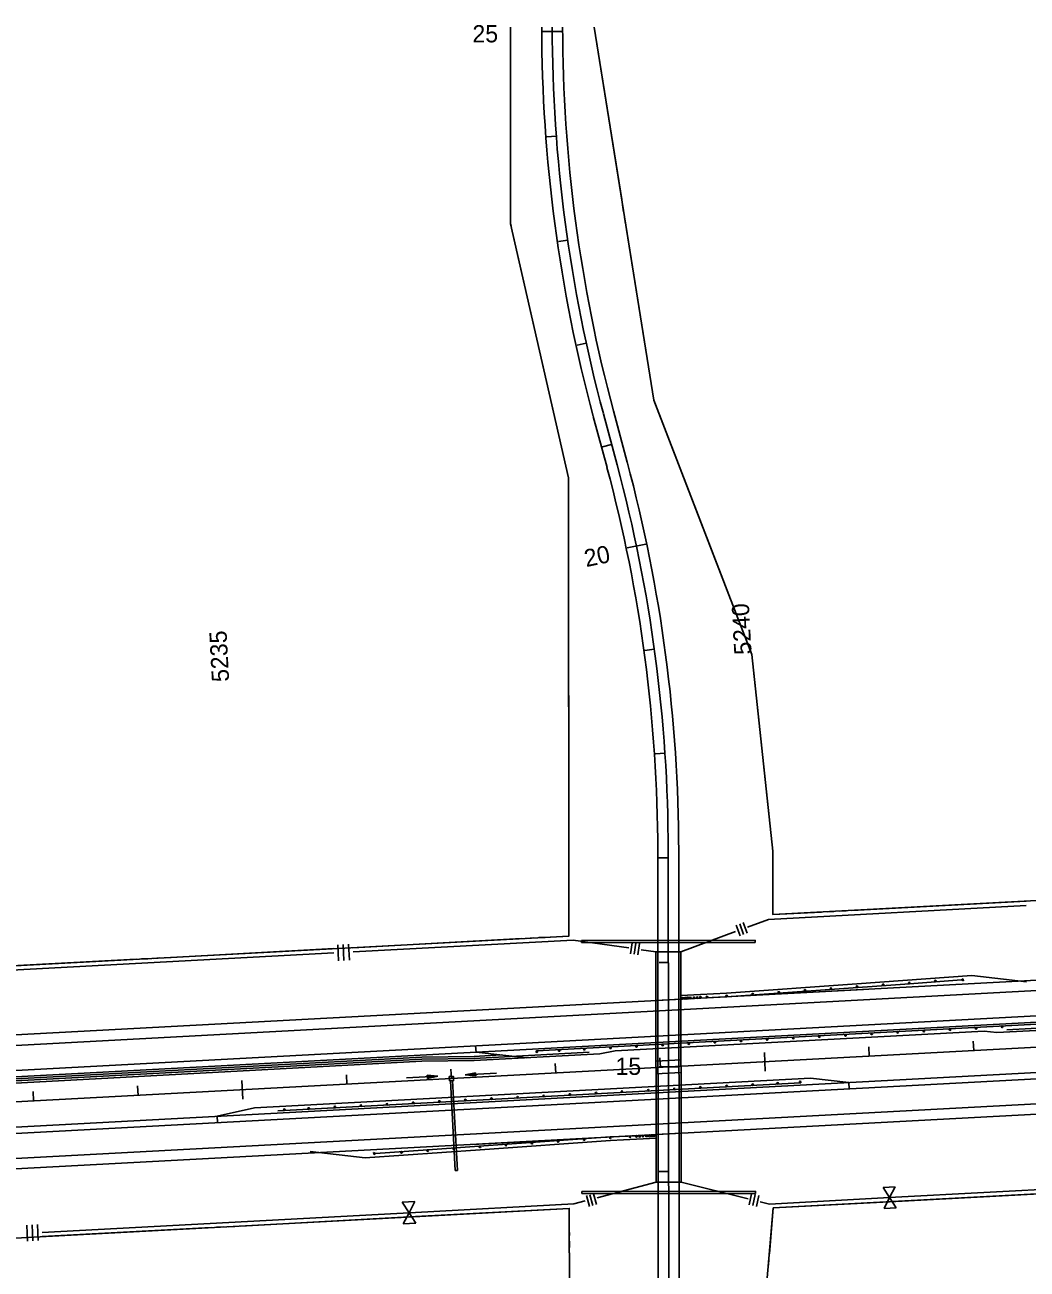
# Model space of a CAD drawing. Extents: x 192699 to 285914, y 194342 to 233219.
# Drawn here: x 267912 to 268870, y 225541 to 226731 of the extents above; entities that cross this region are included whole.
import ezdxf

# ---------------------------------------------------------------- set-up
doc = ezdxf.new("R2010")
doc.units = 0
for name, color, linetype in [('CENT LINE', 7, 'Continuous'), ('CONCRETE', 7, 'Continuous'), ('DRAINAGE', 7, 'Continuous'), ('DRAINAGE ARROWS', 7, 'Continuous'), ('GUARD RAILS', 7, 'Continuous'), ('GUARDRAIL', 7, 'Continuous'), ('R-W - CofA', 7, 'Continuous'), ('R_Draft', 7, 'Continuous'), ('R_Water Annot', 7, 'Continuous'), ('ROAD', 7, 'Continuous'), ('SHOULDER', 7, 'Continuous'), ('STATIONING1', 7, 'Continuous'), ('STATIONING2', 7, 'Continuous'), ('WRSF', 7, 'Continuous')]:
    doc.layers.add(name, color=color, linetype=linetype)

msp = doc.modelspace()

# ---------------------------------------------------------------- linework, layer by layer
at = {"layer": 'CENT LINE'}
for p, q in [((268415.7, 226728.5), (268415.7, 226728.5)), ((268477.7, 226310.2), (268464.6, 226359)), ((268527.8, 224960.5), (268526.6, 225940.8)), ((253740.3, 224942.3), (269263.7, 225774))]:
    msp.add_line(p, q, dxfattribs=at)
for centre, start, end in [((269848.1, 226730.2), 180.0667, 195.0168), ((267094.2, 225939.1), 0.0667, 15.0168)]:
    msp.add_arc(centre, 1432.4, start, end, dxfattribs=at)
at = {"layer": 'CONCRETE'}
for p, q in [((268960.4, 225773.8), (268840.6, 225767.3)), ((268828.5, 225768.7), (268476, 225749.8)), ((268828.5, 225768.7), (268840.6, 225767.3)), ((268367, 225746), (268341.1, 225744.6)), ((268461.1, 225747), (268341.2, 225740.6)), ((268342.9, 225748.7), (268342.5, 225754.7)), ((268342.9, 225748.7), (268391.2, 225743.3)), ((268461.1, 225747), (268476, 225749.8)), ((267077.8, 225678.9), (268291.1, 225743.9)), ((267078, 225674.9), (268291.2, 225739.9)), ((268341.1, 225744.6), (268291.1, 225743.9)), ((268341.2, 225740.6), (268291.2, 225739.9)), ((268131, 225695.3), (268662.7, 225723.8)), ((268699.2, 225719.7), (268662.7, 225723.8)), ((268699.2, 225719.7), (268699.7, 225713.7)), ((268095.4, 225687.4), (268131, 225695.3)), ((268095.4, 225687.4), (268095.7, 225681.4))]:
    msp.add_line(p, q, dxfattribs=at)
at = {"layer": 'DRAINAGE'}
for p, q in [((268443.7, 225855.4), (268609.7, 225855.6)), ((268443.7, 225853.4), (268609.7, 225853.6)), ((268318.5, 225721.3), (268323.1, 225635.5)), ((268320.5, 225721.4), (268325.1, 225635.6)), ((268444, 225615.4), (268610, 225615.6)), ((268444, 225613.4), (268610, 225613.6))]:
    msp.add_line(p, q, dxfattribs=at)
for points in [[(268443.7, 225853.4), (268443.7, 225855.4)], [(268609.7, 225853.6), (268609.7, 225855.6)], [(268323.1, 225635.5), (268325.1, 225635.6)], [(268444, 225613.4), (268444, 225615.4)], [(268610, 225613.6), (268610, 225615.6)]]:
    msp.add_lwpolyline(points, dxfattribs=at)
msp.add_lwpolyline([(268317.5, 225721.3), (268321.5, 225721.5), (268321.3, 225725.5), (268317.3, 225725.3)], close=True, dxfattribs=at)
at = {"layer": 'DRAINAGE ARROWS'}
for p, q in [((268296.2, 225726.5), (268306.3, 225725.6)), ((268296.4, 225723.5), (268296.2, 225726.5)), ((268296.2, 225726.3), (268304.6, 225725.5)), ((268296.3, 225726), (268302.9, 225725.4)), ((268296.3, 225725.8), (268301.3, 225725.3)), ((268296.3, 225725.5), (268299.6, 225725.2)), ((268296.3, 225725.3), (268297.9, 225725.1)), ((268296.3, 225724.6), (268299.6, 225725.2)), ((268296.3, 225724.8), (268297.9, 225725.1)), ((268296.4, 225723.5), (268306.3, 225725.6)), ((268296.4, 225723.8), (268304.6, 225725.5)), ((268296.4, 225724), (268302.9, 225725.4)), ((268296.4, 225724.3), (268301.3, 225725.3)), ((268342.5, 225729), (268332.6, 225727)), ((268342.6, 225726), (268332.6, 225727)), ((268342.5, 225728.8), (268334.2, 225727.1)), ((268342.6, 225726.3), (268334.2, 225727.1)), ((268342.5, 225728.5), (268336, 225727.2)), ((268342.6, 225726.5), (268336, 225727.2)), ((268342.5, 225728.3), (268337.6, 225727.3)), ((268342.6, 225726.8), (268337.6, 225727.3)), ((268342.5, 225728), (268339.3, 225727.4)), ((268342.6, 225727.1), (268339.3, 225727.4)), ((268342.6, 225727.8), (268341, 225727.4)), ((268342.6, 225727.3), (268341, 225727.4)), ((268342.6, 225726), (268342.5, 225729))]:
    msp.add_line(p, q, dxfattribs=at)
at = {"layer": 'GUARD RAILS'}
for p, q in [((268900.2, 225776.6), (268400.9, 225749.8)), ((268153.6, 225692.5), (268652.9, 225719.2))]:
    msp.add_line(p, q, dxfattribs=at)
for centre in [(268770.9, 225768.9), (268795.9, 225770.2), (268820.9, 225771.5), (268845.8, 225772.9), (268546.3, 225756.8), (268571.2, 225758.2), (268596.2, 225759.5), (268621.2, 225760.8), (268646.1, 225762.2), (268671.1, 225763.5), (268696.1, 225764.8), (268721, 225766.2), (268746, 225767.5), (268401, 225749.1), (268422.4, 225750.2), (268446.4, 225751.5), (268471.4, 225752.8), (268496.3, 225754.1), (268521.3, 225755.5), (268457.5, 225709.5), (268482.5, 225710.9), (268507.5, 225712.2), (268532.4, 225713.5), (268557.4, 225714.9), (268582.4, 225716.2), (268607.3, 225717.5), (268631.3, 225718.8), (268652.7, 225720), (268232.9, 225697.5), (268257.8, 225698.8), (268282.8, 225700.2), (268307.8, 225701.5), (268332.7, 225702.8), (268357.7, 225704.2), (268382.7, 225705.5), (268407.6, 225706.8), (268432.6, 225708.2), (268159.7, 225693.6), (268182.9, 225694.8), (268207.9, 225696.1)]:
    msp.add_circle(centre, 0.75, dxfattribs=at)
at = {"layer": 'GUARDRAIL'}
for p, q in [((268562.6, 225800.5), (268713.4, 225808.6)), ((268514.8, 225798), (268538.8, 225799.2)), ((268514.9, 225739.9), (268538.9, 225741.2)), ((268514.9, 225727.9), (268538.9, 225729.1)), ((268491.2, 225668.5), (268339.7, 225660.4)), ((268514.9, 225669.8), (268538.9, 225671.1))]:
    msp.add_line(p, q, dxfattribs=at)
at = {"layer": 'R-W - CofA'}
for p, q in [((268375.9, 226540.5), (268375.7, 226728.5)), ((268431.2, 226297.8), (268375.9, 226540.5)), ((268431.7, 225859.6), (268431.2, 226297.8)), ((268626.7, 225880.1), (269256.3, 225913.8)), ((268591.7, 225870), (268595.4, 225859.9)), ((268595, 225871.2), (268598.7, 225861.2)), ((268598.3, 225872.5), (268602.1, 225862.4)), ((268492, 225853.3), (268490.6, 225842.7)), ((268495.6, 225852.8), (268494.1, 225842.2)), ((268210.8, 225851.3), (268211.6, 225836)), ((268215.9, 225851.6), (268216.7, 225836.3)), ((268221, 225851.9), (268221.8, 225836.6)), ((268499.1, 225852.4), (268497.6, 225841.7)), ((268627, 225599.7), (269271.2, 225634.2)), ((268731.9, 225619.3), (268743.5, 225619.9)), ((268738.2, 225609.6), (268731.9, 225619.3)), ((268743.5, 225619.9), (268738.2, 225609.6)), ((268272.3, 225605.2), (268284.3, 225605.9)), ((268278.9, 225595.1), (268272.3, 225605.2)), ((268284.3, 225605.9), (268278.9, 225595.1)), ((268448.4, 225611.5), (268451.2, 225601.1)), ((268451.8, 225612.4), (268454.6, 225602.1)), ((268455.3, 225613.3), (268458.1, 225603)), ((268606.2, 225613.2), (268603.9, 225602.7)), ((268609.7, 225612.5), (268607.4, 225602)), ((268613.2, 225611.7), (268610.9, 225601.2)), ((268733, 225599.2), (268738.2, 225609.6)), ((268738.2, 225609.6), (268744.6, 225599.9)), ((268273.4, 225584.4), (268278.9, 225595.1)), ((268278.9, 225595.1), (268285.5, 225585)), ((268432, 225599.2), (268432.7, 225019.4)), ((268432, 225599.2), (268432.7, 225019.4)), ((268577.7, 225019.6), (268627, 225599.7)), ((268744.6, 225599.9), (268733, 225599.2)), ((267913.4, 225583.2), (267914.2, 225567.9)), ((267918.5, 225583.5), (267919.3, 225568.2)), ((267923.6, 225583.8), (267924.4, 225568.5)), ((268285.5, 225585), (268273.4, 225584.4))]:
    msp.add_line(p, q, dxfattribs=at)
for points in [[(268375.9, 226561.2), (268375.7, 226728.5)], [(268455.7, 226728.6), (268512.9, 226372)], [(268455.7, 226728.6), (268482.2, 226563.8)], [(268375.9, 226549.8), (268375.9, 226556.1)], [(268483, 226558.5), (268484, 226552.1)], [(268376.4, 226538.5), (268375.9, 226540.5), (268375.9, 226544.6)], [(268484.9, 226546.8), (268485.9, 226540.4)], [(268431.2, 226297.8), (268377.5, 226533.4)], [(268486.7, 226535.1), (268512.9, 226372)], [(268512.9, 226372), (268606.4, 226128.8), (268626.6, 225940.9), (268626.7, 225880.1)], [(268512.9, 226372), (268580.3, 226196.8)], [(268431.3, 226198.6), (268431.2, 226297.8)], [(268431.3, 226187.2), (268431.3, 226193.4)], [(268431.4, 226175.8), (268431.3, 226182)], [(268431.5, 226009.4), (268431.4, 226170.6)], [(268608, 226113.7), (268620.2, 226000.3)], [(268414.2, 225858.7), (268431.7, 225859.6), (268431.5, 226009.4)], [(268620.2, 226000.3), (268626.6, 225940.9), (268626.7, 225880.1), (268673, 225882.5)], [(268622.5, 225875.6), (268868.9, 225888.8)], [(268702, 225884.1), (268868.7, 225893)], [(268678.4, 225882.8), (268684.8, 225883.2)], [(268690.2, 225883.5), (268696.6, 225883.8)], [(268602.5, 225868.2), (268622.5, 225875.6)], [(261904.8, 225509.9), (268431.7, 225859.6)], [(268225.3, 225848.5), (268386.3, 225857.2)], [(268225.5, 225844.5), (268435.7, 225855.7)], [(268391.5, 225857.4), (268397.7, 225857.8)], [(268402.9, 225858.1), (268409.1, 225858.4)], [(268488.8, 225848.3), (268435.7, 225855.7)], [(268538.7, 225844.7), (268590.9, 225863.9)], [(267857.2, 225824.7), (268207.1, 225843.5)], [(268045.9, 225838.9), (268206.9, 225847.6)], [(268514.7, 225844.6), (268500.9, 225846.6)], [(267856.9, 225828.8), (268018, 225837.4)], [(268023.1, 225837.7), (268029.3, 225838)], [(268034.5, 225838.3), (268040.7, 225838.7)], [(268744, 225609.9), (269081.6, 225628)], [(268458.8, 225609.5), (268515, 225624.4)], [(268539, 225624.4), (268603, 225608.5)], [(268284.9, 225595.5), (268436.5, 225603.6)], [(268436.5, 225603.6), (268447.2, 225606.4)], [(268614.4, 225605.7), (268623.5, 225603.4)], [(268623.3, 225555.9), (268627, 225599.7), (268744.2, 225606)], [(268623.5, 225603.4), (268744, 225609.9)], [(268744.2, 225606), (268899.5, 225614.3)], [(261904.6, 225249.5), (268432, 225599.2)], [(261904.6, 225249.5), (268432, 225599.2)], [(267928.1, 225576.3), (268284.9, 225595.5)], [(268117.7, 225582.4), (268285.1, 225591.4)], [(268285.1, 225591.4), (268432, 225599.2), (268432, 225584.8)], [(267928.3, 225572.3), (268089.7, 225580.9)], [(268094.9, 225581.2), (268101.1, 225581.5)], [(268106.3, 225581.8), (268112.5, 225582.1)], [(268432, 225579.6), (268432.1, 225573.3)], [(268432.1, 225568.1), (268432.1, 225561.9)], [(268432.1, 225556.7), (268432.3, 225395.1)], [(268622.4, 225544.9), (268622.9, 225550.9)]]:
    msp.add_lwpolyline(points, dxfattribs=at)
at = {"layer": 'R_Draft'}
for p, q in [((268706.9, 225814), (268816.7, 225821.9)), ((268757.1, 225814.1), (268806.9, 225817.7)), ((268808.6, 225818.8), (268806.9, 225817.7)), ((268808.7, 225816.8), (268806.9, 225817.7)), ((268808.7, 225816.8), (268808.6, 225818.8)), ((268816.7, 225821.9), (268869.2, 225815.9)), ((268557.3, 225803.7), (268582.3, 225805)), ((268582.2, 225805), (268706.9, 225814)), ((268582.5, 225801.5), (268757.1, 225814.1)), ((268557.3, 225803.7), (268538.6, 225802.7)), ((268557.5, 225800.2), (268538.8, 225799.2)), ((268557.5, 225800.2), (268582.5, 225801.5)), ((268471.2, 225667.6), (268296.7, 225655.3)), ((268471.5, 225664.1), (268346.8, 225655.3)), ((268496.2, 225668.8), (268471.2, 225667.6)), ((268496.4, 225665.3), (268471.4, 225664.1)), ((268496.2, 225668.8), (268514.9, 225669.8)), ((268496.4, 225665.3), (268515.1, 225666.3)), ((268237, 225647.6), (268184.5, 225653.7)), ((268346.8, 225655.3), (268237, 225647.6)), ((268245, 225652.7), (268246.8, 225651.8)), ((268245, 225652.7), (268245.1, 225650.7)), ((268245.1, 225650.7), (268246.8, 225651.8)), ((268296.7, 225655.3), (268246.8, 225651.8))]:
    msp.add_line(p, q, dxfattribs=at)
for centre in [(268782, 225816.6), (268632.3, 225805.8), (268657.3, 225807.6), (268682.2, 225809.4), (268707.1, 225811.2), (268732.1, 225813), (268757, 225814.8), (268540.3, 225800.1), (268541.9, 225800.1), (268543.4, 225800.2), (268545, 225800.3), (268546.6, 225800.4), (268548.1, 225800.5), (268551.2, 225800.6), (268554.4, 225800.8), (268557.5, 225801), (268563.7, 225801.3), (268582.5, 225802.3), (268607.4, 225804.1), (268396.5, 225661.6), (268421.4, 225663.3), (268446.3, 225665.1), (268471.3, 225666.8), (268490, 225667.8), (268496.3, 225668.1), (268499.4, 225668.2), (268502.5, 225668.4), (268505.6, 225668.6), (268507.2, 225668.6), (268508.7, 225668.7), (268510.3, 225668.8), (268511.9, 225668.9), (268513.4, 225668.9), (268271.7, 225652.8), (268296.7, 225654.6), (268321.6, 225656.3), (268346.6, 225658.1), (268371.5, 225659.8)]:
    msp.add_circle(centre, 0.75, dxfattribs=at)
at = {"layer": 'R_Water Annot'}
for p, q in [((268276.3, 225724), (268306.3, 225725.6)), ((268296.2, 225726.5), (268306.3, 225725.6)), ((268296.4, 225723.5), (268296.2, 225726.5)), ((268296.2, 225726.3), (268304.6, 225725.5)), ((268296.3, 225726), (268302.9, 225725.4)), ((268296.3, 225725.8), (268301.3, 225725.3)), ((268296.3, 225725.5), (268299.6, 225725.2)), ((268296.3, 225725.3), (268297.9, 225725.1)), ((268296.3, 225724.6), (268299.6, 225725.2)), ((268296.3, 225724.8), (268297.9, 225725.1)), ((268296.4, 225723.5), (268306.3, 225725.6)), ((268296.4, 225723.8), (268304.6, 225725.5)), ((268296.4, 225724), (268302.9, 225725.4)), ((268296.4, 225724.3), (268301.3, 225725.3)), ((268342.5, 225729), (268332.6, 225727)), ((268362.5, 225728.7), (268332.6, 225727)), ((268342.6, 225726), (268332.6, 225727)), ((268342.5, 225728.8), (268334.2, 225727.1)), ((268342.6, 225726.3), (268334.2, 225727.1)), ((268342.5, 225728.5), (268336, 225727.2)), ((268342.6, 225726.5), (268336, 225727.2)), ((268342.5, 225728.3), (268337.6, 225727.3)), ((268342.6, 225726.8), (268337.6, 225727.3)), ((268342.5, 225728), (268339.3, 225727.4)), ((268342.6, 225727.1), (268339.3, 225727.4)), ((268342.6, 225727.8), (268341, 225727.4)), ((268342.6, 225727.3), (268341, 225727.4)), ((268342.6, 225726), (268342.5, 225729))]:
    msp.add_line(p, q, dxfattribs=at)
at = {"layer": 'ROAD'}
for p, q in [((268468.1, 226307.6), (268455, 226356.4)), ((268487.4, 226312.8), (268474.3, 226361.6)), ((268517.8, 224960.5), (268516.6, 225940.8)), ((268537.8, 224960.5), (268536.6, 225940.8)), ((268538.7, 225844.7), (268514.7, 225844.6)), ((268514.7, 225844.6), (268515, 225624.4)), ((268539, 225624.4), (268538.7, 225844.7)), ((265550.1, 225629.1), (269260.9, 225827.9)), ((265536.9, 225604.4), (269262.1, 225803.9)), ((265503.9, 225542.5), (269265.4, 225744)), ((265490.7, 225517.8), (269266.6, 225720.1)), ((268515, 225624.4), (268539, 225624.4))]:
    msp.add_line(p, q, dxfattribs=at)
for centre, radius, start, end in [((269848.1, 226730.2), 1442.4, 180.0667, 195.0168), ((269848.1, 226730.2), 1422.4, 180.0667, 195.0168), ((267094.2, 225939.1), 1422.4, 0.0667, 15.0168), ((267094.2, 225939.1), 1442.4, 0.0667, 15.0168)]:
    msp.add_arc(centre, radius, start, end, dxfattribs=at)
at = {"layer": 'SHOULDER'}
for p, q in [((266153.7, 225671.5), (269260.3, 225837.9)), ((266177.5, 225632.7), (269262.5, 225798)), ((266180.1, 225584.7), (269265, 225750)), ((266083.3, 225539.5), (269267.2, 225710.1))]:
    msp.add_line(p, q, dxfattribs=at)
at = {"layer": 'STATIONING1'}
for points in [[(268818.2, 225759.1), (268818.7, 225750.1)], [(268618.5, 225748.4), (268619.4, 225730.5)], [(268718.3, 225753.8), (268718.8, 225744.8)], [(268418.7, 225737.7), (268419.2, 225728.7)], [(268518.6, 225743.1), (268519.1, 225734.1)], [(268119.2, 225721.7), (268120.1, 225703.7)], [(268219, 225727), (268219.5, 225718)], [(268318.9, 225732.4), (268319.4, 225723.4)], [(267919.5, 225711), (267919.9, 225702)], [(268019.3, 225716.3), (268019.8, 225707.3)]]:
    msp.add_lwpolyline(points, dxfattribs=at)
at = {"layer": 'STATIONING2'}
for points in [[(268406.7, 226724.2), (268424.7, 226724.3)], [(268410.7, 226623.6), (268419.6, 226624.3)], [(268421.6, 226523.6), (268430.5, 226524.9)], [(268439.5, 226424.6), (268448.3, 226426.5)], [(268463.8, 226327.2), (268472.5, 226329.5)], [(268487.5, 226230.6), (268505.1, 226234.3)], [(268504.4, 226132.7), (268513.3, 226133.9)], [(268514.5, 226033.8), (268523.5, 226034.4)], [(268517.6, 225934.5), (268526.6, 225934.5)], [(268517.8, 225834.5), (268526.8, 225834.5)], [(268517.9, 225734.5), (268535.9, 225734.5)], [(268518, 225634.5), (268527, 225634.5)]]:
    msp.add_lwpolyline(points, dxfattribs=at)
at = {"layer": 'WRSF'}
for p, q in [((268960.3, 225775.8), (268850.4, 225769.9)), ((268451, 225748.5), (268341.2, 225742.6)), ((267077.9, 225676.9), (268291.1, 225741.9)), ((268341.2, 225742.6), (268291.1, 225741.9))]:
    msp.add_line(p, q, dxfattribs=at)

# ---------------------------------------------------------------- texts
at = {"layer": 'STATIONING1'}
for s, p in [('5240', (268606.3, 226129.1)), ('5235', (268107, 226103))]:
    msp.add_text(s, height=16.5, rotation=93.0667, dxfattribs=at).set_placement(p)
at = {"layer": 'STATIONING2'}
for s, rotation, p in [('25', 0.2377, (268339.5, 226713.9)), ('20', 11.8164, (268448.2, 226212.3)), ('15', 0.0667, (268476.2, 225726.9))]:
    msp.add_text(s, height=16.5, rotation=rotation, dxfattribs=at).set_placement(p)

doc.saveas('drawing.dxf')
